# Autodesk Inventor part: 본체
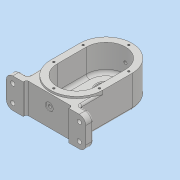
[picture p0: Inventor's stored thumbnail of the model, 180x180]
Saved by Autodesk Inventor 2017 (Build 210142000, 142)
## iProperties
Part Number: 본체
Material: 일반
Document SubType Name: Modeling
Designer: MRC
Density: 1 g/cm^3
Appearance: 기본값
Author: MRC
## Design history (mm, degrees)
sketch "스케치1"
  geometry: L1 (0, 0)-(0, -45); L2 (-40, 0)-(-40, -45); L3 (40, -45)-(40, 0); A1 r 40 centre (0, 0) between (40, 0) and (-40, 0); A2 r 40 centre (0, -45) between (-40, -45) and (40, -45); 1 further point
  constraints: 8 end point, 4 point on circle, 4 tangent, 2 centre point, 1 midpoint, 1 parallel, 1 vertical
  dimensions: "d0" = 45 distance of L1.start L1.end; "d1" = 80 diameter of A2
extrude "돌출1" new body sketch "스케치1" distance "d2" = 21; taper "d4" = 0 deg; dims "d3" = 28, "d5" = 0
sketch "스케치2"
  geometry: L1 (0, 0)-(0, -45); L2 (-30, 0)-(-30, -45); L3 (30, -45)-(30, 0); A1 r 40 centre (0, -45) between (-40, -45) and (40, -45) reference; A2 r 40 centre (0, 0) between (40, 0) and (-40, 0) reference; A3 r 30 centre (0, 0) between (30, 0) and (-30, 0); A4 r 30 centre (0, -45) between (-30, -45) and (30, -45); 1 further point
  constraints: 8 end point, 4 point on circle, 4 tangent, 2 centre point, 1 midpoint, 1 parallel, 1 vertical
  dimensions: "d6" = 30 radius of A3
extrude "돌출2" cut sketch "스케치2" distance "d7" = 41; taper "d8" = 0 deg
sketch "스케치3"
  geometry: L1 (0, 0)-(0, -45); L2 (-26, 0)-(-26, -45); L3 (26, -45)-(26, 0); A1 r 40 centre (0, 0) between (40, 0) and (-40, 0) reference; A2 r 40 centre (0, -45) between (-40, -45) and (40, -45) reference; A3 r 26 centre (0, 0) between (26, 0) and (-26, 0); A4 r 26 centre (0, -45) between (-26, -45) and (26, -45); 1 further point
  constraints: 8 end point, 4 point on circle, 4 tangent, 2 centre point, 1 midpoint, 1 parallel, 1 vertical
  dimensions: "d9" = 52 diameter of A4
extrude "돌출3" join sketch "스케치3" distance "d10" = 11; taper "d11" = 0 deg
sketch "스케치4"
  geometry: L1 (-26, 0)-(-26, -45) reference; L2 (26, -45)-(26, 0) reference; L3 (-26, -30)-(26, -30); A1 r 26 centre (0, 0) between (26, 0) and (-26, 0) reference
  constraints: 2 end point, 2 point on line, 1 perpendicular
  dimensions: "d12" = 30 distance from line of A1.centre L3
extrude "돌출4" cut sketch "스케치4" distance "d13" = 3; taper "d14" = 0 deg
hole "구멍1" diameter "d17" = 22; stored, may be unused: countersink angle "d21" = 90 deg, drill point angle "d23" = 118 deg; dims "d15" = 10, "d16" = 10, "d18" = 6, "d19" = 28, "d20" = 8, "d22" = 8
sketch "스케치5"
  geometry: C1 r 11 at (0, 0) reference; C2 r 14 at (0, 0); A1 r 26 centre (0, 0) between (26, 0) and (-26, 0) reference
  constraints: 1 centre point, 1 coincident
  dimensions: "d24" = 28 diameter of C2
extrude "돌출5" cut sketch "스케치5" distance "d25" = 4; taper "d26" = 0 deg
hole "구멍2" diameter "d32" = 20; stored, may be unused: countersink angle "d36" = 90 deg, drill point angle "d38" = 0 deg; dims "d30" = 10, "d31" = 10, "d33" = 6, "d34" = 28, "d35" = 8, "d37" = 12
fillet "모깎기1" dims "d39" = 3
fillet "모깎기2" dims "d40" = 0.3
chamfer "모따기2" distance "d41" = 1; stored, may be unused: second distance "d42" = 2, angle "d43" = 45 deg
sketch "스케치6"
  geometry: L1 (-40, 0)-(-40, -45) reference; L2 (-40, -45)-(-40, -80); L3 (-40, -80)-(-61, -80); L4 (-61, -80)-(-61, -92); L5 (-61, -92)-(61, -92); L6 (61, -92)-(61, -80); L7 (61, -80)-(40, -80); L8 (-40, -80)-(-40, -45); L9 (40, -45)-(40, -80); A1 r 26 centre (0, 0) between (26, 0) and (-26, 0) reference; A2 r 40 centre (0, -45) between (-40, -45) and (40, -45) reference; A3 r 40 centre (0, -45) between (-40, -45) and (40, -45) reference; 1 further point
  constraints: 16 end point, 5 perpendicular, 5 tangent, 3 point on line, 1 collinear, 1 midpoint, 1 vertical, 1 vertical alignment
  dimensions: "d44" = 12 distance of L5.end L6.end; "d45" = 92 distance from line of L5 A1.centre; "d46" = 122 distance of L4.end L5.end
extrude "돌출6" join sketch "스케치6" distance "d47" = 46; taper "d48" = 0 deg
sketch "스케치7"
  geometry: L1 (-61, -92)-(61, -92) reference; L2 (-35, -87)-(35, -87); L3 (35, -87)-(35, -92); L4 (35, -92)-(-35, -92); L5 (-35, -92)-(-35, -87); 1 further point
  constraints: 8 end point, 2 midpoint, 2 parallel, 1 horizontal, 1 perpendicular
  dimensions: "d49" = 70 distance of L3.end L4.end; "d50" = 5 distance of L2.end L3.end
extrude "돌출7" cut sketch "스케치7" stored distance "d51" = 46; taper "d52" = 0 deg
sketch "스케치10"
  geometry: A1 r 26 centre (0, 0) between (26, 0) and (-26, 0) reference; 1 further point
  constraints: 1 vertical alignment
  dimensions: "d75" = 20 distance of A1.centre point (0, 20)
hole "구멍5" sketch "스케치10" at (0, 20) diameter "d76" = 3.242; stored, may be unused: countersink angle "d80" = 90 deg, drill point angle "d82" = 118 deg; dims "d77" = 8, "d78" = 28, "d79" = 8, "d81" = 10
fillet "모깎기3" dims "d86" = 10
sketch "스케치11"
  geometry: A1 r 10 centre (-11, 10) between (-21, 10) and (-11, 0) reference; A2 r 10 centre (-11, 36) between (-11, 46) and (-21, 36) reference; 3 further points
  constraints: 2 coincident
hole "구멍6" sketch "스케치11" at (-11, 36), (-11, 10) diameter "d87" = 6.6; stored, may be unused: countersink angle "d91" = 90 deg, drill point angle "d93" = 118 deg; dims "d88" = 8, "d89" = 11, "d90" = 2, "d92" = 10
fillet "모깎기4" dims "d94" = 3
node "작업 평면1"
sketch "스케치12"
  geometry: C1 r 6 at (35, 28); 1 further point
  constraints: 1 centre point, 1 coincident
  dimensions: "d96" = 12 diameter of C1
extrude "돌출8" join sketch "스케치12" stored distance "d97" = 46; taper "d98" = 0 deg
hole "구멍7" diameter "d101" = 4.917; stored, may be unused: countersink angle "d105" = 90 deg, drill point angle "d107" = 118 deg; dims "d99" = 10, "d100" = 10, "d102" = 12, "d103" = 11, "d104" = 2, "d106" = 17.1
sketch "스케치14"
  geometry: L1 (-51, -92)-(-35, -92) reference; L2 (-32, -87)-(32, -87) reference; 2 further points
  constraints: 1 midpoint, 1 vertical alignment, 1 other
  dimensions: "d126" = 12 distance from line of point (0, -80) L1
feature "엠보싱1" sketch "스케치14" dims "d0" = 45, "d1" = 80, "d127" = 0.5, "d128" = 0
fillet "모깎기5" dims "d129" = 3
fillet "모깎기6" dims "d130" = 5
sketch "스케치15"
  geometry: L1 (-40, 0)-(-40, -45) reference; L2 (40, -45)-(40, 0) reference; L3 (-35, 0)-(-35, -45); L4 (35, -45)-(35, 0); A1 r 30 centre (0, 0) between (30, 0) and (-30, 0) reference; A2 r 40 centre (0, -45) between (-40, -45) and (40, -45) reference; A3 r 40 centre (0, 0) between (40, 0) and (-40, 0) reference; A4 r 35 centre (0, -45) between (-35, -45) and (35, -45); A5 r 35 centre (0, 0) between (35, 0) and (-35, 0); 6 further points
  constraints: 6 point on circle, 4 coincident, 4 end point, 2 centre point, 3 other
  dimensions: "d131" = 5 radial gap between concentric circles of A5 A1
hole "구멍10" sketch "스케치15" at (0, 35), (-35, 0), (-35, -45), (0, -80), (35, -45), (35, 0) diameter "d132" = 3.242; stored, may be unused: countersink angle "d136" = 90 deg, drill point angle "d138" = 118 deg; dims "d133" = 8, "d134" = 4, "d135" = 2, "d137" = 10
sketch "스케치16"
  geometry: L1 (72, 49)-(-8, 49) reference; 2 further points
  constraints: 1 coincident
  dimensions: "d139" = 21 distance from line of point (32, 28) L1
hole "구멍11" sketch "스케치16" at (32, 28) diameter "d140" = 4.917; stored, may be unused: countersink angle "d144" = 90 deg, drill point angle "d146" = 118 deg; dims "d141" = 12, "d142" = 12, "d143" = 1, "d145" = 17.1
node "솔리드1"
pattern_circular "원형 패턴3" dims angle "d84" = 360 deg
mirror "미러1"
other parameters: "d95" = -135
